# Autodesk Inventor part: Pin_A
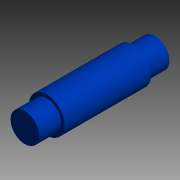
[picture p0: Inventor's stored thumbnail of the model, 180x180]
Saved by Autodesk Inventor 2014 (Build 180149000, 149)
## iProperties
Shininess: 0.0
Length Units: 11272
Angle Units: 11279
Time Units: 11290
Mass Units: 11283
Length Display Precision: 2
Angle Display Precision: 1
Compacted: True
Created: 1999-05
Part Number: Pin_A
Document SubType Name: Modeling
Designer: Administrator
Density: 7.84 g/cm^3
Material: Steel, High Strength Low Alloy
Mass: 9.6691 g
Surface Area: 7.61176 cm^2
Volume: 1.2333 cm^3
Appearance: Blue - Semi Gloss
Density: 0.0
Volumn: 0.0
Area: 0.0
PropertySet Name: Model Information
Control State: 0
Master: False
Checked Out: False
Author: Administrator
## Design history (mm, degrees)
node "y-z Plane"
  node "x-z Plane"
  node "x-y Plane"
node "Extrusion1" dims "d1" = 19.05, "d2" = 0
  sketch "Sketch1"
    geometry: C1 r 3.937 at (0, 0); 1 further point
    constraints: 1 centre point, 1 coincident
    dimensions: "d0" = 7.874 diameter of C1
node "Extrusion2" dims "d4" = 4.826, "d5" = 0
  sketch "Sketch2"
    geometry: C1 r 3.937 at (0, 0) reference; C2 r 3.175 at (0, 0)
    constraints: 1 centre point
    dimensions: "d3" = 6.35 diameter of C2
node "Extrusion3" dims "d7" = 4.826, "d8" = 0
  sketch "Sketch3"
    geometry: C1 r 3.937 at (0, 0) reference; C2 r 3.175 at (0, 0)
    constraints: 1 centre point
    dimensions: "d6" = 6.35 diameter of C2
body "Solid1"
